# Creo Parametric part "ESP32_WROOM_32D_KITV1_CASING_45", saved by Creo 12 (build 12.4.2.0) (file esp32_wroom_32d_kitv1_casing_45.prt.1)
Units: Custom; MM, KILOGRAM, SECS

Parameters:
  PTC_WM_ITERATION = "0"
  PTC_WM_VERSION = "-.0"
  PTC_WM_LIFECYCLE_STATE = "In Work"
  PTC_WM_LIFECYCLE = "MO_CADDocument"
  PTC_WM_CREATED_BY = "Maximilian Roepper (Z0017RMS: MO)"
  PTC_WM_CREATED_ON = "18-Sep-26 11:36:42 AM"
  PTC_WM_MODIFIED_BY = "Maximilian Roepper (Z0017RMS: MO)"
  PTC_WM_MODIFIED_ON = "18-Sep-26 11:36:46 AM"
  PDMLINKNUMBER = "PDM000071455320"
  PTC_WM_NAME = "esp32_wroom_32d_kitv1_casing_45.prt"
  PTC_WM_NUMBER = "PDM000071455320"

Other parameters: WEIGHT, WEIGHT_FACTOR, WEIGHT_ADD, _MASS_TEMP, _DIFF_TEMP, MC_ERRORS, SUPPLIER

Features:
  1. coordinate system
  2. datum plane "PRT_YZ"
  3. datum plane "PRT_XY"
  4. datum plane "PRT_XZ"
  5. coordinate system
  6. datum axis
  7. datum axis
  8. datum axis
  9. coordinate system
  10. imported feature
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
Other named items: PRT, SIEMENS_MO, DRW_VIEW_ORG, PRT_X, PRT_Y, PRT_Z, CS0, ROUGH_GROB

Layers: 00_STD_CSYS-KSYS, 01_STD_PLANES-EBENEN, 02_STD_AXES-ACHSEN, 03_STD_CSYS-KSYS, 24_IMPORT_FEAT-IMPORT_KE

Surfaces: 6 plane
